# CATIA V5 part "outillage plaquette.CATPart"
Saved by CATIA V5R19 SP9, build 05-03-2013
Part number: outillage plaquette
Bounding box of the stored display mesh (mm): x -150 to 150, y -150 to 150, z -10 to 0
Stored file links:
  C:\Users\herve.bezard\Downloads\etiquette Soline\outillage plaquette.CATPart
  C:\Users\herve.bezard\Downloads\etiquette Soline\CN etiquette.CATProduct
  C:\Users\herve.bezard\Downloads\etiquette Soline\etiquette bois.CATPart
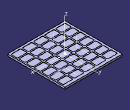
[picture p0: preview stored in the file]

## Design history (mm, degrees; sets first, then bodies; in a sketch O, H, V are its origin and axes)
AxisSystem1: origin (0, 0, 0), X (1, 0, 0), Y (0, 1, 0), Z (0, 0, 1)
Set1
  DatumSurface1: linked copy from another document
Body1 (main body)
  Sketch1 on XY plane of AxisSystem1, origin (0, 0, 0), H (1, 0, 0), V (0, 1, 0)
    line L1 (150, 150) -> (150, -150)
    line L2 (150, -150) -> (-150, -150)
    line L3 (-150, -150) -> (-150, 150)
    line L4 (-150, 150) -> (150, 150)
    length L2 = 300
    length L3 = 300
    vertical: L1 V, L3 V
    horizontal: L2 H, L4 H
    equidistance: L1 L3 O, L2 L4 O
  Pad1: profile Sketch1, direction (0, 0, -1), length 10
  Sketch2 on start face of Pad1, origin (0, 0, 0), H (1, 0, 0), V (0, 1, 0)
    point P17 (-88.2324, -134.2452)
    point P18 (-88.2324, -110.2452)
    point P19 (-88.2324, -134.2452)
    point P20 (-93.2324, -139.2452)
    point P21 (-134.5324, -139.2452)
    point P22 (-93.2324, -139.2452)
    point P23 (-134.5324, -139.2452)
    point P24 (-139.5324, -134.2452)
    point P25 (-139.5324, -110.2452)
    point P26 (-139.5324, -134.2452)
    point P27 (-139.5324, -110.2452)
    point P28 (-134.5324, -105.2452)
    point P29 (-93.2324, -105.2452)
    point P30 (-134.5324, -105.2452)
    point P31 (-93.2324, -105.2452)
    point P32 (-88.2324, -110.2452)
    line L1 (-88.2324, -110.2452) -> (-88.2324, -134.2452)
    arc A1 centre (-93.2324, -134.2452) radius 5 from (-93.2324, -139.2452) to (-88.2324, -134.2452) ccw
    line L2 (-93.2324, -139.2452) -> (-134.5324, -139.2452)
    arc A2 centre (-134.5324, -134.2452) radius 5 from (-139.5324, -134.2452) to (-134.5324, -139.2452) ccw
    line L3 (-139.5324, -134.2452) -> (-139.5324, -110.2452)
    arc A3 centre (-134.5324, -110.2452) radius 5 from (-134.5324, -105.2452) to (-139.5324, -110.2452) ccw
    line L4 (-134.5324, -105.2452) -> (-93.2324, -105.2452)
    arc A4 centre (-93.2324, -110.2452) radius 5 from (-88.2324, -110.2452) to (-93.2324, -105.2452) ccw
    coincidence: P17 P19, P18 P32, P20 P22, P21 P23, P24 P26, P25 P27, P28 P30, P29 P31
  Pocket1: profile Sketch2, direction (0, 0, -1), length 1
  RectPattern1: of Pocket1, direction 1 instances 5, spacing 58, along X axis, direction 2 instances 7, spacing 40, along Y axis
  Sketch3 on start face of Pad1, origin (0, 0, 0), H (1, 0, 0), V (0, 1, 0)
    line L1 (150, 150) -> (150, -150)
    line L2 (150, -150) -> (-150, -150)
    line L3 (-150, -150) -> (-150, 150)
    line L4 (-150, 150) -> (150, 150)
    length L2 = 300
    length L3 = 300
    vertical: L1 V, L3 V
    horizontal: L2 H, L4 H
    equidistance: L1 L3 O, L2 L4 O
  Pad2: profile Sketch3, direction (0, 0, -1), length 10
Current feature: RectPattern1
